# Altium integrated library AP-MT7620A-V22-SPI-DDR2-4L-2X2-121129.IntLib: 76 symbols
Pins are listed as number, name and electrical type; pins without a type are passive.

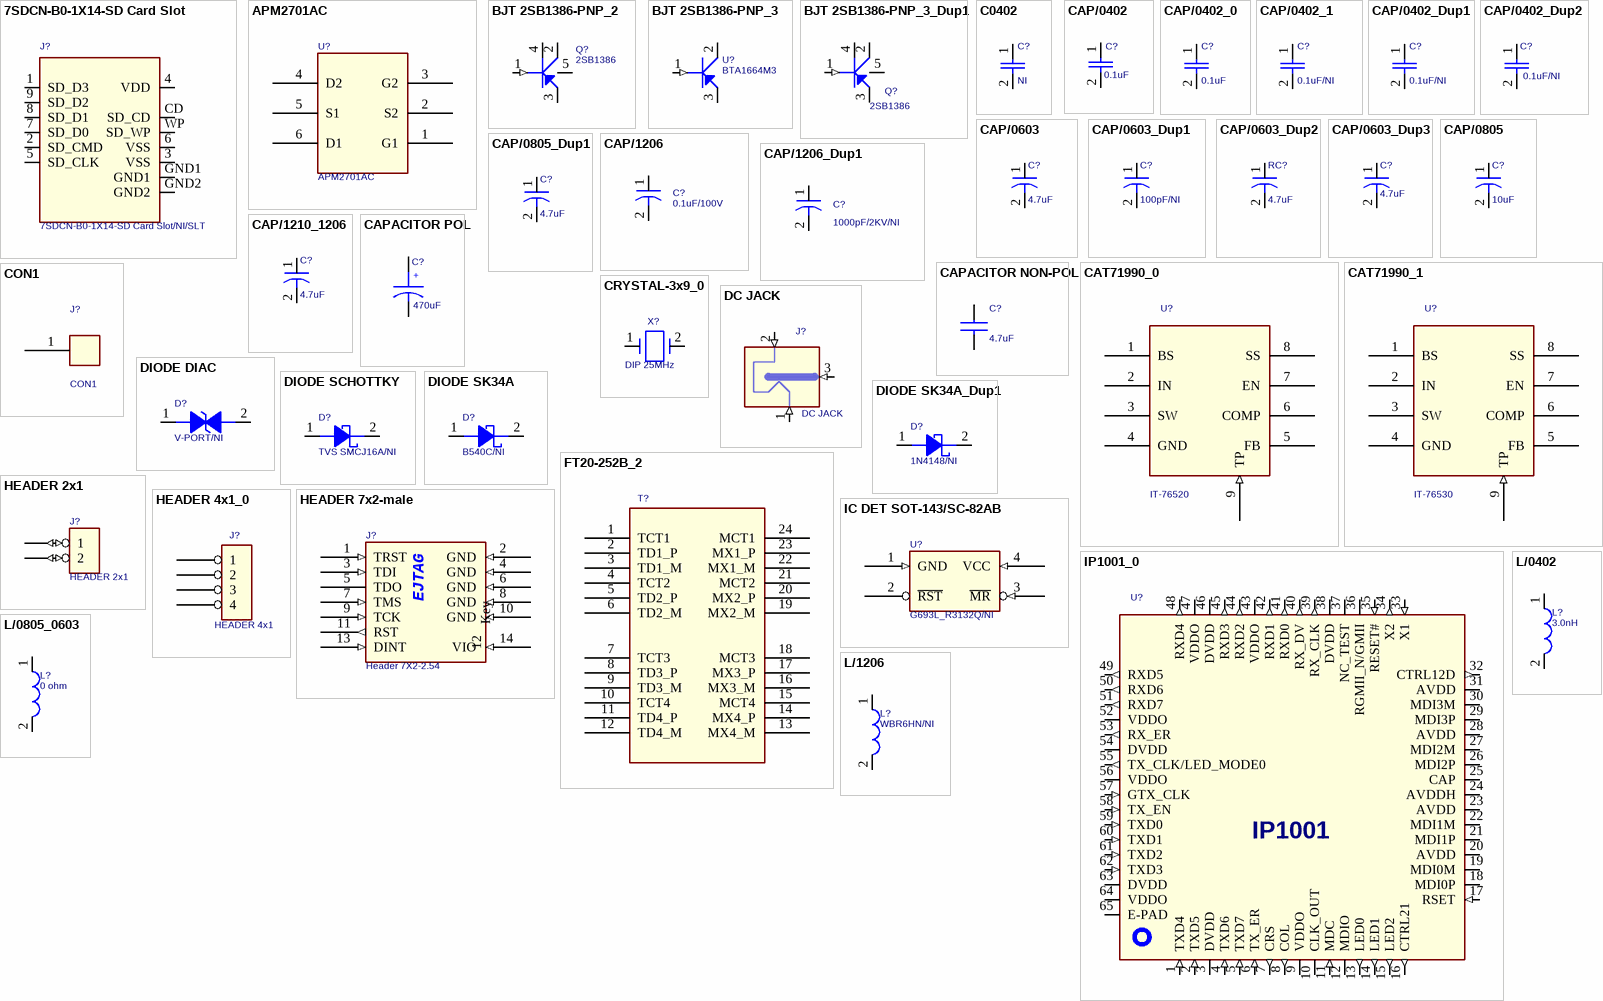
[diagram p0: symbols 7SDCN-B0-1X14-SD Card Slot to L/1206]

## 7SDCN-B0-1X14-SD Card Slot
designator J?, comment 7SDCN-B0-1X14-SD Card Slot/NI/SLT
footprint CON10P/SMD/R/F/7SDCN-B0-1X14
footprint CON10P/SMD/R/F/7SDCN-B0-1X14
pins: 1 SD_D3, 2 SD_CMD, 3 VSS, 4 VDD, 5 SD_CLK, 6 VSS, 7 SD_D0, 8 SD_D1, 9 SD_D2, CD SD_CD, GND1, GND2, WP SD_WP

## APM2701AC
designator U?
footprint SOT-23-6/SMD/P0.95/APM2701AC
pins: 1 G1, 2 S2, 3 G2, 4 D2, 5 S1, 6 D1

## BJT 2SB1386-PNP_2
designator Q?, comment 2SB1386
footprint SOT-89
footprint SOT-89/SMD/2SB1386
pins: 1 BASE (in), 2 COLLECTOR (io), 3 EMITTER (io), 4 COLLECTOR (io), 5 COLLECTOR (io)

## BJT 2SB1386-PNP_3
designator U?, comment BTA1664M3
footprint SOT-89
footprint SOT89/SMD
pins: 1 BASE (in), 2 COLLECTOR (io), 3 EMITTER (io)

## BJT 2SB1386-PNP_3_Dup1
designator Q?, comment 2SB1386
footprint SOT-89
footprint SOT-89/SMD/2SB1386
pins: 1 BASE (in), 2 COLLECTOR (power), 3 EMITTER (io), 4 COLLECTOR, 5 COLLECTOR

## C0402
designator C?, comment NI
footprint C0402
footprint C0402
pins: 1, 2

## CAP/0402
designator C?, comment 0.1uF
footprint 0402
footprint C0402
pins: 1 (io), 2 (io)

## CAP/0402_0
designator C?, comment 0.1uF
footprint 0402
footprint C0402
pins: 1, 2

## CAP/0402_1
designator C?, comment 0.1uF/NI
footprint 0402
footprint C0402
pins: 1, 2

## CAP/0402_Dup1
designator C?, comment 0.1uF/NI
footprint 0402
footprint C0402
pins: 1 (io), 2 (io)

## CAP/0402_Dup2
designator C?, comment 0.1uF/NI
1st Part Field: 0402
footprint 0402
footprint C0402
pins: 1, 2

## CAP/0603
designator C?, comment 4.7uF
footprint 0603
footprint C0603
pins: 1, 2

## CAP/0603_Dup1
designator C?, comment 100pF/NI
footprint 0603
footprint C0603
pins: 1, 2

## CAP/0603_Dup2
designator RC?, comment 4.7uF
footprint 0603
footprint C0603
pins: 1, 2

## CAP/0603_Dup3
designator C?, comment 4.7uF
footprint 0603
footprint C0603
pins: 1, 2

## CAP/0805
designator C?, comment 10uF
footprint 0805
footprint C0805
pins: 1, 2

## CAP/0805_Dup1
designator C?, comment 4.7uF
footprint 0805
footprint C0805
pins: 1, 2

## CAP/1206
designator C?, comment 0.1uF/100V
footprint 1206
footprint SB/1206
pins: 1, 2

## CAP/1206_Dup1
designator C?, comment 1000pF/2KV/NI
footprint 1206
footprint C1206
pins: 1, 2

## CAP/1210_1206
designator C?, comment 4.7uF
footprint 1210/1206
footprint C0805
pins: 1, 2

## CAPACITOR NON-POL
designator C?, comment 4.7uF
footprint C0603
pins: 1, 2

## CAPACITOR POL
designator C?, comment 470uF
footprint C470UF16V/D8H11
pins: 1, 2

## CAT71990_0
designator U?, comment IT-76520
footprint SOP8
footprint SOP8/SMD/P1.27/IT7653
pins: 1 BS, 2 IN, 3 SW, 4 GND, 5 FB, 6 COMP, 7 EN, 8 SS, 9 TP (in)

## CAT71990_1
designator U?, comment IT-76530
footprint SOP8
footprint SOP8/SMD/P1.27/IT7653
pins: 1 BS, 2 IN, 3 SW, 4 GND, 5 FB, 6 COMP, 7 EN, 8 SS, 9 TP (in)

## CON1
designator J?
footprint P1//M
pins: 1

## CRYSTAL-3x9_0
designator X?, comment DIP 25MHz
footprint XTAL-DIP-3X9
footprint CRYS/DIP/D5X10.6/GB2000025/eCERA
pins: 1, 2

## DC JACK
designator J?
footprint DC-JACK
footprint DC-JACK/3P/DIP/R/JD003-PF
pins: 1 (in), 2 (in), 3 (in)

## DIODE DIAC
designator D?, comment V-PORT/NI
PartNo: 3500-00000530
footprint C0603
pins: 1, 2

## DIODE SCHOTTKY
designator D?, comment TVS SMCJ16A/NI
footprint DO-214AB
footprint VARISTOR/SMD/TVM5B150L103RY
pins: 1 ANODE, 2 CATHODE

## DIODE SK34A
designator D?, comment B540C/NI
footprint DO-214AC
footprint D/SMD/P6.61/B540C
pins: 1 ANODE, 2 CATHODE

## DIODE SK34A_Dup1
designator D?, comment 1N4148/NI
footprint DO-214AC
footprint C0402
pins: 1 ANODE, 2 CATHODE

## FT20-252B_2
designator T?, comment FT20-252B  (value not drawn)
footprint TRANSFORMER/24P/SMD/HN2429CG
pins: 1 TCT1, 2 TD1_P, 3 TD1_M, 4 TCT2, 5 TD2_P, 6 TD2_M, 7 TCT3, 8 TD3_P, 9 TD3_M, 10 TCT4, 11 TD4_P, 12 TD4_M, 13 MX4_M, 14 MX4_P, 15 MCT4, 16 MX3_M, 17 MX3_P, 18 MCT3, 19 MX2_M, 20 MX2_P, 21 MCT2, 22 MX1_M, 23 MX1_P, 24 MCT1

## HEADER 2x1
designator J?
footprint P2x1-2.54mm
footprint DIP2/P2.54
pins: 1 (io), 2 (io)

## HEADER 4x1_0
designator J?, comment HEADER 4x1
footprint P4x1-2.54mm
footprint DIP4/P2.54
pins: 1, 2, 3, 4

## HEADER 7x2-male
designator J?, comment Header 7X2-2.54
footprint P7x2-2.54mm
footprint DIP7X2/P2.54
pins: 1 TRST (in), 2 GND (in), 3 TDI (in), 4 GND (in), 5 TDO (hiz), 6 GND (in), 7 TMS (in), 8 GND (in), 9 TCK (in), 10 GND (in), 11 RST (out), 12 Key, 13 DINT (in), 14 VIO (in)

## IC DET SOT-143/SC-82AB
designator U?, comment G693L_R3132Q/NI
footprint SOT-143/SC-82AB
footprint SOT-143/SMD/G693
pins: 1 GND (in), 2 ~{RST} (oc), 3 ~{MR} (in), 4 VCC (in)

## IP1001_0
designator U?, comment IP1001
footprint QFN64/SMD/P0.5/IP1001
pins: 1 TXD4 (in), 2 TXD5 (in), 3 DVDD (power), 4 TXD6 (in), 5 TXD7 (in), 6 TX_ER (in), 7 CRS (out), 8 COL (out), 9 VDDO (power), 10 CLK_OUT (power), 11 MDC (in), 12 MDIO (io), 13 LED0 (out), 14 LED1 (out), 15 LED2 (out), 16 CTRL21 (out), 17 RSET (in), 18 MDI0P (io), 19 MDI0M (io), 20 AVDD (power), 21 MDI1P (io), 22 MDI1M (io), 23 AVDD (power), 24 AVDDH (power), 25 CAP, 26 MDI2P (io), 27 MDI2M (io), 28 AVDD (power), 29 MDI3P (io), 30 MDI3M (io), 31 AVDD (power), 32 CTRL12D (out), 33 X1 (in), 34 X2 (out), 35 RESET# (in), 36 RGMII_N/GMII, 37 NC_TEST, 38 DVDD (power), 39 RX_CLK (out), 40 RX_DV (out), 41 RXD0 (out), 42 RXD1 (out), 43 VDDO (power), 44 RXD2 (out), 45 RXD3 (out), 46 DVDD (power), 47 VDDO (power), 48 RXD4 (out), 49 RXD5 (out), 50 RXD6 (out), 51 RXD7 (out), 52 VDDO (power), 53 RX_ER (out), 54 DVDD (power), 55 TX_CLK/LED_MODE0 (out), 56 VDDO (power), 57 GTX_CLK (in), 58 TX_EN (in), 59 TXD0 (in), 60 TXD1 (in), 61 TXD2 (in), 62 TXD3 (in), 63 DVDD (power), 64 VDDO (power), 65 E-PAD (power)

## L/0402
designator L?, comment 3.0nH
footprint 0402
footprint L0402
pins: 1, 2

## L/0805_0603
designator L?, comment 0 ohm
footprint 0805/0603
footprint L0805
pins: 1, 2

## L/1206
designator L?, comment WBR6HN/NI
footprint 1206
footprint L/IND/DIP/D6H14
pins: 1, 2

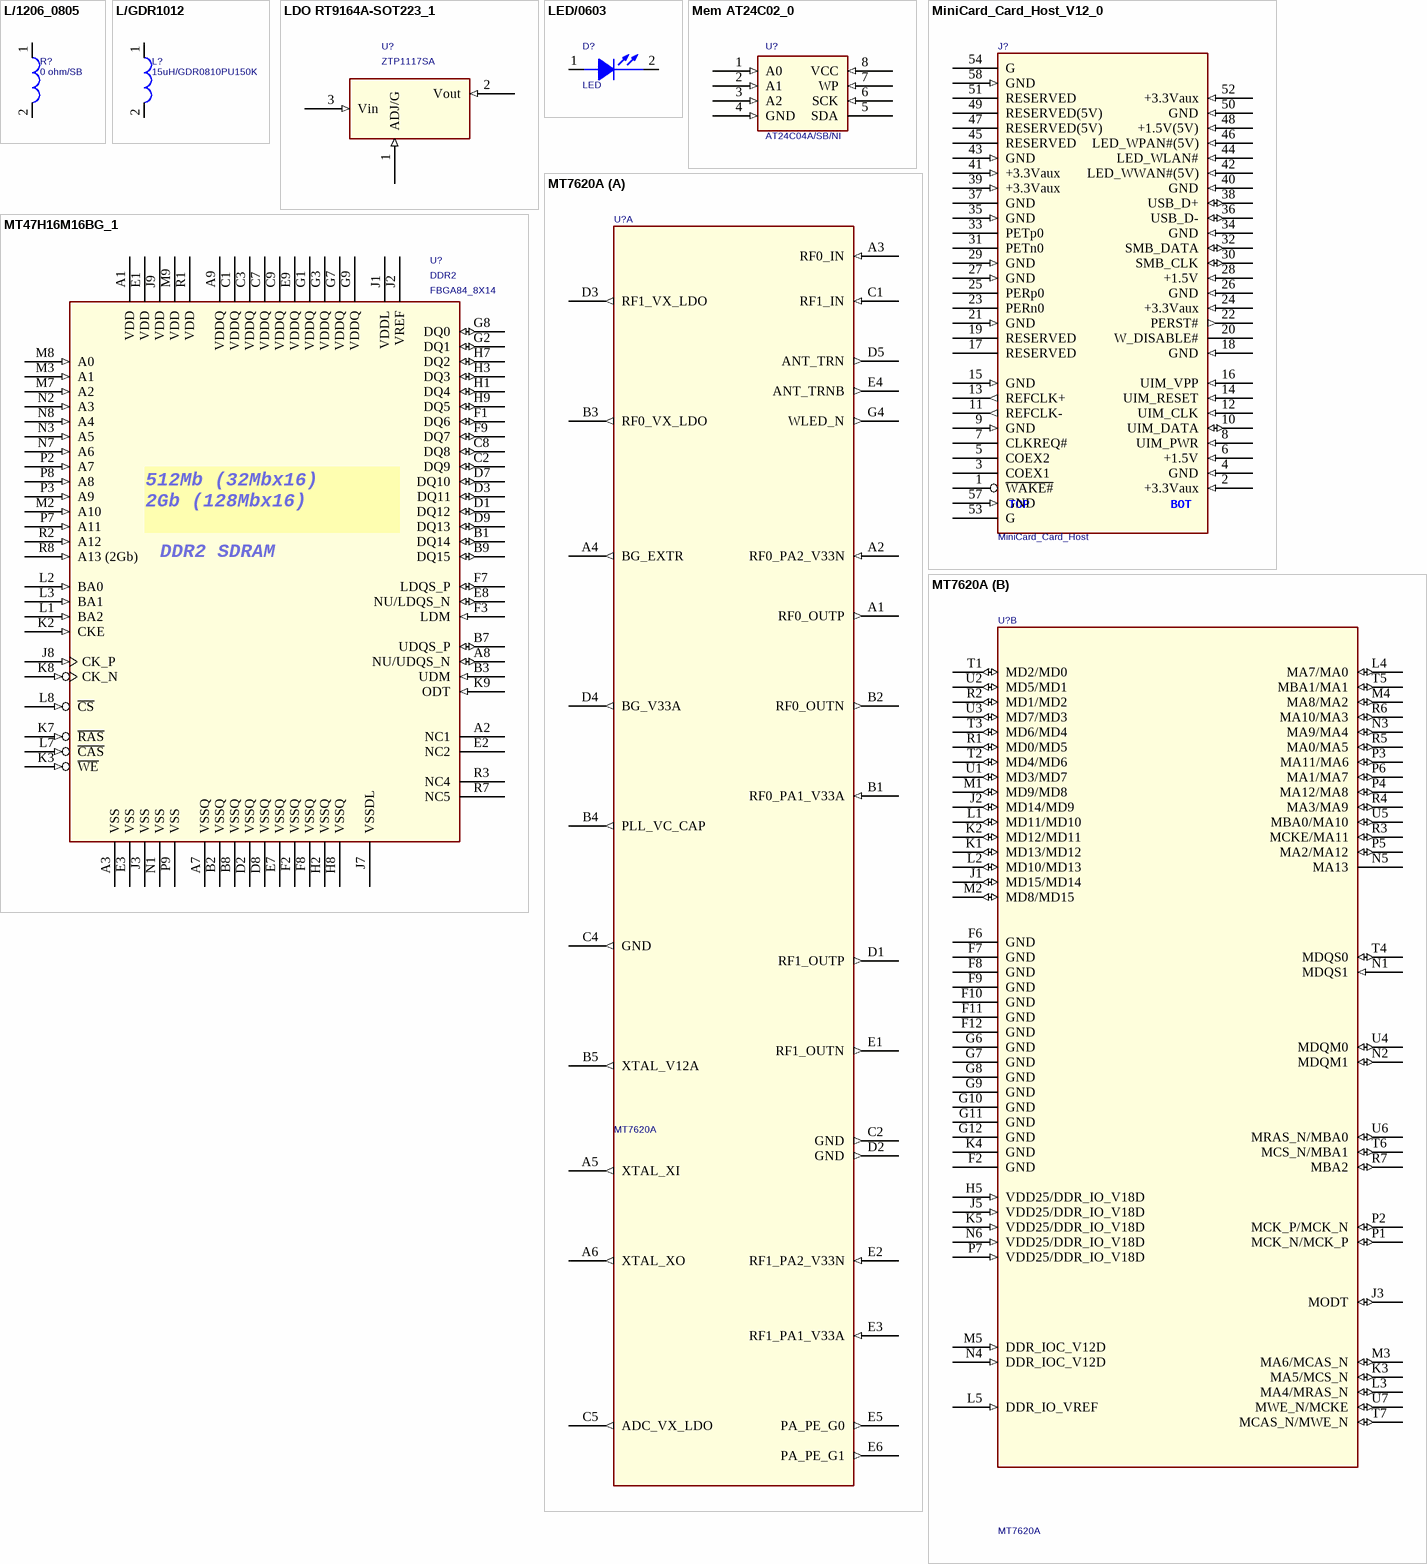
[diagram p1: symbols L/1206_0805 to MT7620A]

## L/1206_0805
designator R?, comment 0 ohm/SB
footprint 1206/0805
footprint SB/0603
pins: 1, 2

## L/GDR1012
designator L?, comment 15uH/GDR0810PU150K
footprint GDR-1012
footprint L/IND/DIP/MCD-0808-150MU-J
pins: 1, 2

## LDO RT9164A-SOT223_1
designator U?, comment ZTP1117SA
footprint SOT223-3/SMD/P2.3/AX1007
footprint SOT223-3/SMD/P2.3/AX1007
pins: 1 ADJ/G (in), 2 Vout (in), 3 Vin (in)

## LED/0603
designator D?, comment LED
footprint 0603
footprint C0603
pins: 1 ANODE, 2 CATHODE

## Mem AT24C02_0
designator U?, comment AT24C04A/SB/NI
footprint SOIC-8
footprint SOIC8/SMD/P1.27/AT24C04B-08B
pins: 1 A0 (in), 2 A1 (in), 3 A2 (in), 4 GND (in), 5 SDA, 6 SCK (in), 7 WP (in), 8 VCC (in)

## MiniCard_Card_Host_V12_0
designator J?, comment MiniCard_Card_Host
footprint PCIe-MiniCard-half
footprint MINI-PCI-Express/52P/SMD/R/F/C1720007
pins: 1 ~{WAKE#} (oc), 2 +3.3Vaux (in), 3 COEX1, 4 GND (in), 5 COEX2, 6 +1.5V (in), 7 CLKREQ# (oc), 8 UIM_PWR (in), 9 GND (in), 10 UIM_DATA (io), 11 REFCLK- (out), 12 UIM_CLK (in), 13 REFCLK+ (out), 14 UIM_RESET (in), 15 GND (in), 16 UIM_VPP (in), 17 RESERVED, 18 GND (in), 19 RESERVED, 20 W_DISABLE#, 21 GND (in), 22 PERST# (out), 23 PERn0, 24 +3.3Vaux (in), 25 PERp0, 26 GND (in), 27 GND (in), 28 +1.5V (in), 29 GND (in), 30 SMB_CLK (io), 31 PETn0, 32 SMB_DATA (io), 33 PETp0, 34 GND (in), 35 GND (in), 36 USB_D- (io), 37 GND (power), 38 USB_D+ (io), 39 +3.3Vaux (in), 40 GND (in), 41 +3.3Vaux (in), 42 LED_WWAN#(5V) (in), 43 GND (in), 44 LED_WLAN# (in), 45 RESERVED, 46 LED_WPAN#(5V) (in), 47 RESERVED(5V), 48 +1.5V(5V) (in), 49 RESERVED(5V), 50 GND (in), 51 RESERVED, 52 +3.3Vaux (in), 53 G, 54 G, 57 GND (in), 58 GND (in)

## MT47H16M16BG_1
designator U?, comment DDR2  Package: FBGA84_8X14
IC-SDRAM-MT47H-FBGA84; NC: A2,E2,L1,R3,R7,R8; Vendor PN: MT47H16M16BG-5E; Vendor: MICRON; Description 2: 5nS 32MX16 DDR2; P_Number: xx; P_Description: W9725G6IB
footprint WBGA84/SMD/P0.8/W9751G6IB
pins: A1 VDD (power), A2 NC1, A3 VSS (power), A7 VSSQ (power), A8 NU/UDQS_N (io), A9 VDDQ (power), B1 DQ14 (io), B2 VSSQ (power), B3 UDM (in), B7 UDQS_P (io), B8 VSSQ (power), B9 DQ15 (io), C1 VDDQ (power), C2 DQ9 (io), C3 VDDQ (power), C7 VDDQ (power), C8 DQ8 (io), C9 VDDQ (power), D1 DQ12 (io), D2 VSSQ (power), D3 DQ11 (io), D7 DQ10 (io), D8 VSSQ (power), D9 DQ13 (io), E1 VDD (power), E2 NC2, E3 VSS (power), E7 VSSQ (power), E8 NU/LDQS_N (io), E9 VDDQ (power), F1 DQ6 (io), F2 VSSQ (power), F3 LDM (in), F7 LDQS_P (io), F8 VSSQ (power), F9 DQ7 (io), G1 VDDQ (power), G2 DQ1 (io), G3 VDDQ (power), G7 VDDQ (power), G8 DQ0 (io), G9 VDDQ (power), H1 DQ4 (io), H2 VSSQ (power), H3 DQ3 (io), H7 DQ2 (io), H8 VSSQ (power), H9 DQ5 (io), J1 VDDL (power), J2 VREF (power), J3 VSS (power), J7 VSSDL (power), J8 CK_P (in), J9 VDD (power), K2 CKE (in), K3 ~{WE} (in), K7 ~{RAS} (in), K8 CK_N (in), K9 ODT (in), L1 BA2 (in), L2 BA0 (in), L3 BA1 (in), L7 ~{CAS} (in), L8 ~{CS} (in), M2 A10 (in), M3 A1 (in), M7 A2 (in), M8 A0 (in), M9 VDD (power), N1 VSS (power), N2 A3 (in), N3 A5 (in), N7 A6 (in), N8 A4 (in), P2 A7 (in), P3 A9 (in), P7 A11 (in), P8 A8 (in), P9 VSS (power), R1 VDD (power), R2 A12 (in), R3 NC4, R7 NC5, R8 A13 (2Gb) (in)

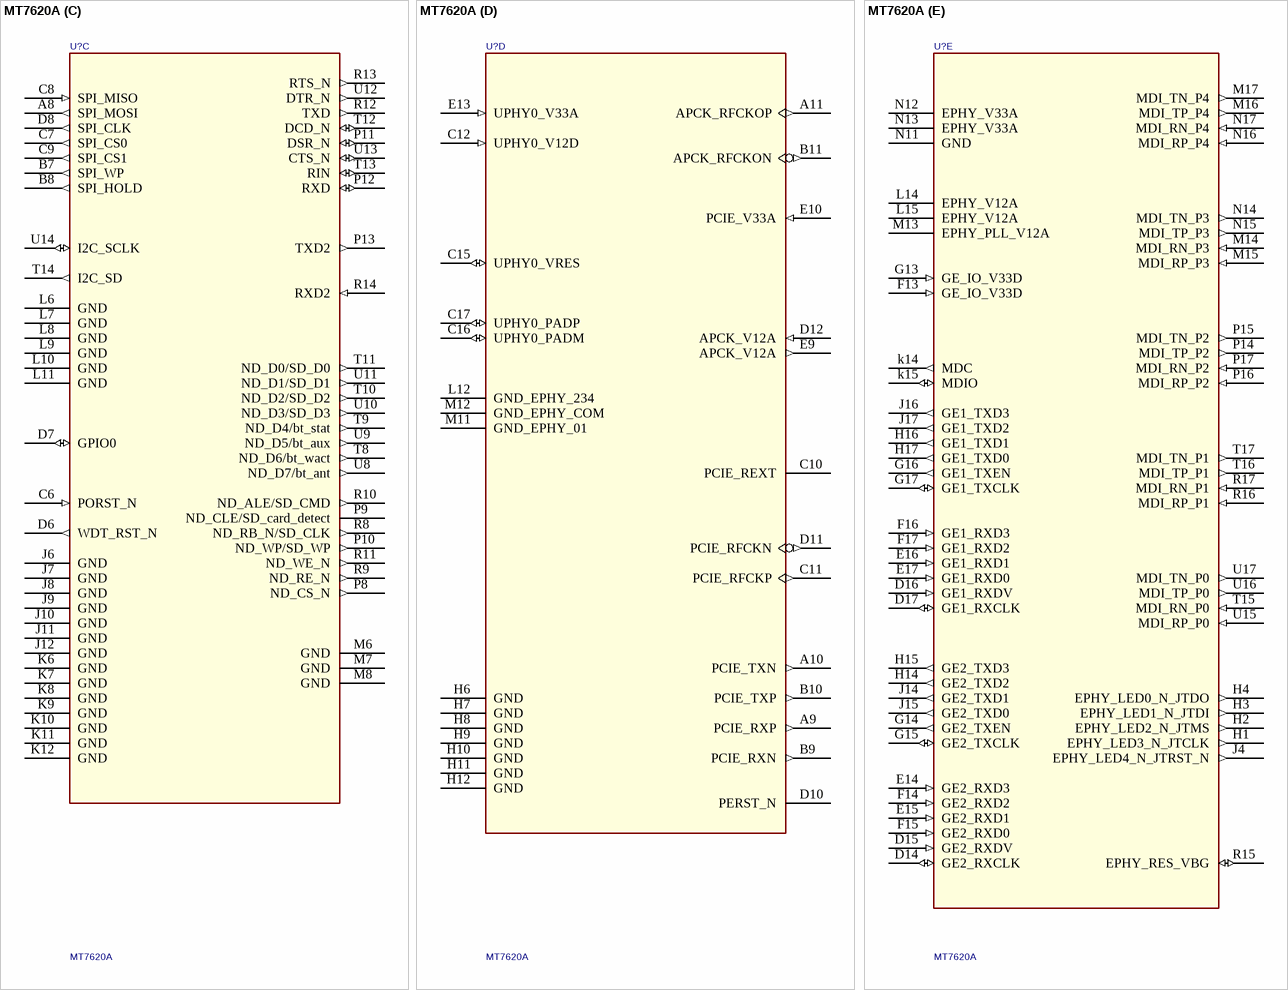
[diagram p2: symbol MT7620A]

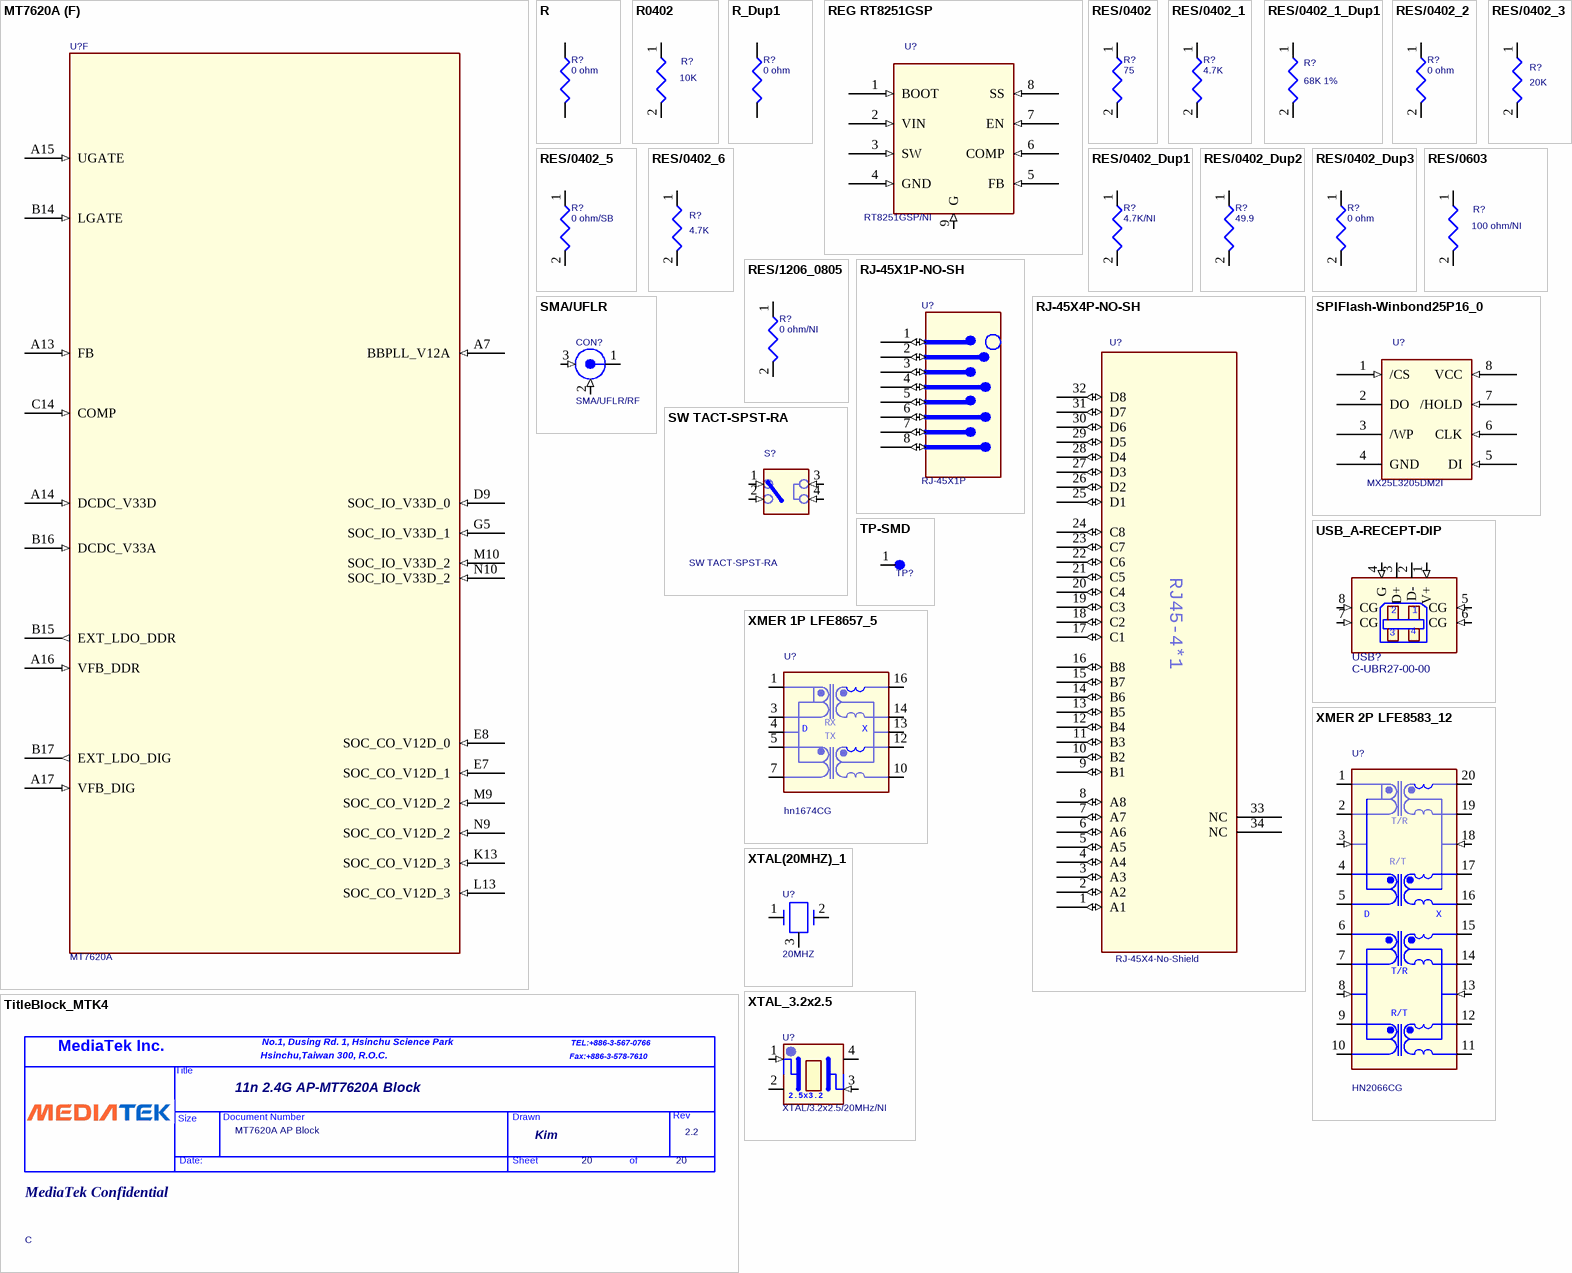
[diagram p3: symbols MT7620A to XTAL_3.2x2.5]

## MT7620A
designator U?
footprint MT7620AE2/TFBGA265/P0.65/B0.3/11X11
footprint MT7620AE2/TFBGA265/P0.65/B0.3/11X11
part A pins: A1 RF0_OUTP (out), A2 RF0_PA2_V33N (in), A3 RF0_IN (in), A4 BG_EXTR (out), A5 XTAL_XI (out), A6 XTAL_XO (out), B1 RF0_PA1_V33A (in), B2 RF0_OUTN (out), B3 RF0_VX_LDO (out), B4 PLL_VC_CAP (out), B5 XTAL_V12A (out), C1 RF1_IN (in), C2 GND (out), C4 GND (out), C5 ADC_VX_LDO (out), D1 RF1_OUTP (out), D2 GND (out), D3 RF1_VX_LDO (out), D4 BG_V33A (out), D5 ANT_TRN (out), E1 RF1_OUTN (out), E2 RF1_PA2_V33N (in), E3 RF1_PA1_V33A (in), E4 ANT_TRNB (out), E5 PA_PE_G0 (out), E6 PA_PE_G1 (out), G4 WLED_N (out)
part B pins: F2 GND (power), F6 GND (power), F7 GND (power), F8 GND (power), F9 GND (power), F10 GND (power), F11 GND (power), F12 GND (power), G6 GND (power), G7 GND (power), G8 GND (power), G9 GND (power), G10 GND (power), G11 GND (power), G12 GND (power), H5 VDD25/DDR_IO_V18D (in), J1 MD15/MD14 (io), J2 MD14/MD9 (io), J3 MODT (io), J5 VDD25/DDR_IO_V18D (in), K1 MD13/MD12 (io), K2 MD12/MD11 (io), K3 MA5/MCS_N (io), K4 GND (power), K5 VDD25/DDR_IO_V18D (in), L1 MD11/MD10 (io), L2 MD10/MD13 (io), L3 MA4/MRAS_N (io), L4 MA7/MA0 (io), L5 DDR_IO_VREF (in), M1 MD9/MD8 (io), M2 MD8/MD15 (io), M3 MA6/MCAS_N (io), M4 MA8/MA2 (io), M5 DDR_IOC_V12D (in), N1 MDQS1 (in), N2 MDQM1 (io), N3 MA9/MA4 (io), N4 DDR_IOC_V12D (in), N5 MA13, N6 VDD25/DDR_IO_V18D (in), P1 MCK_N/MCK_P (io), P2 MCK_P/MCK_N (io), P3 MA11/MA6 (io), P4 MA12/MA8 (io), P5 MA2/MA12 (io), P6 MA1/MA7 (io), P7 VDD25/DDR_IO_V18D (in), R1 MD0/MD5 (io), R2 MD1/MD2 (io), R3 MCKE/MA11 (io), R4 MA3/MA9 (io), R5 MA0/MA5 (io), R6 MA10/MA3 (io), R7 MBA2 (io), T1 MD2/MD0 (io), T2 MD4/MD6 (io), T3 MD6/MD4 (io), T4 MDQS0 (io), T5 MBA1/MA1 (io), T6 MCS_N/MBA1 (io), T7 MCAS_N/MWE_N (io), U1 MD3/MD7 (io), U2 MD5/MD1 (io), U3 MD7/MD3 (io), U4 MDQM0 (io), U5 MBA0/MA10 (io), U6 MRAS_N/MBA0 (io), U7 MWE_N/MCKE (io)
part C pins: A8 SPI_MOSI (out), B7 SPI_WP (out), B8 SPI_HOLD (out), C6 PORST_N (in), C7 SPI_CS0 (out), C8 SPI_MISO (in), C9 SPI_CS1 (out), D6 WDT_RST_N (out), D7 GPIO0 (io), D8 SPI_CLK (out), J6 GND (power), J7 GND (power), J8 GND (power), J9 GND (power), J10 GND (power), J11 GND (power), J12 GND (power), K6 GND (power), K7 GND (power), K8 GND (power), K9 GND (power), K10 GND (power), K11 GND (power), K12 GND (power), L6 GND (power), L7 GND (power), L8 GND (power), L9 GND (power), L10 GND (power), L11 GND (power), M6 GND (power), M7 GND (power), M8 GND (power), P8 ND_CS_N (out), P9 ND_CLE/SD_card_detect, P10 ND_WP/SD_WP (out), P11 DSR_N (io), P12 RXD (io), P13 TXD2 (out), R8 ND_RB_N/SD_CLK (out), R9 ND_RE_N (out), R10 ND_ALE/SD_CMD (out), R11 ND_WE_N (out), R12 TXD (out), R13 RTS_N (out), R14 RXD2 (in), T8 ND_D6/bt_wact (out), T9 ND_D4/bt_stat (out), T10 ND_D2/SD_D2 (out), T11 ND_D0/SD_D0 (out), T12 DCD_N (io), T13 RIN (io), T14 I2C_SD (out), U8 ND_D7/bt_ant (out), U9 ND_D5/bt_aux (out), U10 ND_D3/SD_D3 (out), U11 ND_D1/SD_D1 (out), U12 DTR_N (out), U13 CTS_N (io), U14 I2C_SCLK (io)
part D pins: A9 PCIE_RXP (out), A10 PCIE_TXN (out), A11 APCK_RFCKOP (out), B9 PCIE_RXN (out), B10 PCIE_TXP (out), B11 APCK_RFCKON (out), C10 PCIE_REXT, C11 PCIE_RFCKP (out), C12 UPHY0_V12D (in), C15 UPHY0_VRES (io), C16 UPHY0_PADM (io), C17 UPHY0_PADP (io), D10 PERST_N, D11 PCIE_RFCKN (out), D12 APCK_V12A (in), E9 APCK_V12A (out), E10 PCIE_V33A (in), E13 UPHY0_V33A (in), H6 GND (power), H7 GND (power), H8 GND (power), H9 GND (power), H10 GND (power), H11 GND (power), H12 GND (power), L12 GND_EPHY_234 (power), M11 GND_EPHY_01 (power), M12 GND_EPHY_COM (power)
part E pins: D14 GE2_RXCLK (io), D15 GE2_RXDV (in), D16 GE1_RXDV (in), D17 GE1_RXCLK (io), E14 GE2_RXD3 (in), E15 GE2_RXD1 (in), E16 GE1_RXD1 (in), E17 GE1_RXD0 (in), F13 GE_IO_V33D (in), F14 GE2_RXD2 (in), F15 GE2_RXD0 (in), F16 GE1_RXD3 (in), F17 GE1_RXD2 (in), G13 GE_IO_V33D (in), G14 GE2_TXEN (out), G15 GE2_TXCLK (io), G16 GE1_TXEN (out), G17 GE1_TXCLK (io), H1 EPHY_LED3_N_JTCLK (out), H2 EPHY_LED2_N_JTMS (out), H3 EPHY_LED1_N_JTDI (out), H4 EPHY_LED0_N_JTDO (out), H14 GE2_TXD2 (out), H15 GE2_TXD3 (out), H16 GE1_TXD1 (out), H17 GE1_TXD0 (out), J4 EPHY_LED4_N_JTRST_N (out), J14 GE2_TXD1 (out), J15 GE2_TXD0 (out), J16 GE1_TXD3 (out), J17 GE1_TXD2 (out), k14 MDC (out), k15 MDIO (io), L14 EPHY_V12A (power), L15 EPHY_V12A (power), M13 EPHY_PLL_V12A (power), M14 MDI_RN_P3 (in), M15 MDI_RP_P3 (in), M16 MDI_TP_P4 (out), M17 MDI_TN_P4 (out), N11 GND (power), N12 EPHY_V33A (power), N13 EPHY_V33A (power), N14 MDI_TN_P3 (out), N15 MDI_TP_P3 (out), N16 MDI_RP_P4 (in), N17 MDI_RN_P4 (in), P14 MDI_TP_P2 (out), P15 MDI_TN_P2 (out), P16 MDI_RP_P2 (in), P17 MDI_RN_P2 (in), R15 EPHY_RES_VBG (io), R16 MDI_RP_P1 (in), R17 MDI_RN_P1 (in), T15 MDI_RN_P0 (in), T16 MDI_TP_P1 (out), T17 MDI_TN_P1 (out), U15 MDI_RP_P0 (in), U16 MDI_TP_P0 (out), U17 MDI_TN_P0 (out)
part F pins: A7 BBPLL_V12A (in), A13 FB (in), A14 DCDC_V33D (in), A15 UGATE (in), A16 VFB_DDR (in), A17 VFB_DIG (in), B14 LGATE (in), B15 EXT_LDO_DDR (out), B16 DCDC_V33A (in), B17 EXT_LDO_DIG (out), C14 COMP (in), D9 SOC_IO_V33D_0 (in), E7 SOC_CO_V12D_1 (in), E8 SOC_CO_V12D_0 (in), G5 SOC_IO_V33D_1 (in), K13 SOC_CO_V12D_3 (in), L13 SOC_CO_V12D_3 (in), M9 SOC_CO_V12D_2 (in), M10 SOC_IO_V33D_2 (in), N9 SOC_CO_V12D_2 (in), N10 SOC_IO_V33D_2 (in)

## R
designator R?, comment 0 ohm
Resistor, 0603, 5%; Part Number: 110-110-00100; Manufacturer: �j驾�歆�; Class: 1R-0402; Key: 3162U-N14-V11-#449; SDTSourceLibName: C:\WINDOWS\TEMP\2GM.LIB; V1: 25V 20%; By: Ralink; HYP_Type: (R; BOM_Class: Chipset
footprint L0805
pins: 1, 2

## R0402
designator R?, comment 10K
footprint R0402
footprint R0402
pins: 1, 2

## R_Dup1
designator R?, comment 0 ohm
footprint R0805
pins: 1, 2

## REG RT8251GSP
designator U?, comment RT8251GSP/NI
footprint SOIC-8P-EP
footprint SOP8/SMD/P1.27/RT8251
pins: 1 BOOT (in), 2 VIN (in), 3 SW (in), 4 GND (in), 5 FB (in), 6 COMP (in), 7 EN (in), 8 SS (in), 9 G (in)

## RES/0402
designator R?, comment 75
footprint 0402
footprint R0402
pins: 1 (io), 2 (io)

## RES/0402_1
designator R?, comment 4.7K
footprint 0402
footprint R0402
pins: 1, 2

## RES/0402_1_Dup1
designator R?, comment 68K 1%
footprint 0402
footprint R0402
pins: 1, 2

## RES/0402_2
designator R?, comment 0 ohm
footprint 0402
footprint R0402
pins: 1, 2

## RES/0402_3
designator R?, comment 20K
footprint 0402
footprint R0402
pins: 1, 2

## RES/0402_5
designator R?, comment 0 ohm/SB
footprint 0402
footprint SB/0402
pins: 1, 2

## RES/0402_6
designator R?, comment 4.7K
footprint 0402
footprint R0402
pins: 1, 2

## RES/0402_Dup1
designator R?, comment 4.7K/NI
footprint 0402
footprint R0402
pins: 1 (io), 2 (io)

## RES/0402_Dup2
designator R?, comment 49.9
footprint 0402
footprint R0402
pins: 1 (io), 2 (io)

## RES/0402_Dup3
designator R?, comment 0 ohm
footprint 0402
footprint R0402
pins: 1 (io), 2 (io)

## RES/0603
designator R?, comment 100 ohm/NI
footprint 0603
footprint R0603
pins: 1 (io), 2 (io)

## RES/1206_0805
designator R?, comment 0 ohm/NI
footprint 1206/0805
footprint C1206
pins: 1 (io), 2 (io)

## RJ-45X1P-NO-SH
designator U?, comment RJ-45X1P
footprint RJ45A-NO-SH
footprint RJ45/8P/DIP/R/8208C-B01
pins: 1 P1 (io), 2 P2 (io), 3 P3 (io), 4 P4 (io), 5 P5 (io), 6 P6 (io), 7 P7 (io), 8 P8 (io)

## RJ-45X4P-NO-SH
designator U?, comment RJ-45X4-No-Shield
footprint RJ45-4P-NO-SH
footprint RJ45/32P/DIP/R/N3642-001
pins: 1 A1 (io), 2 A2 (io), 3 A3 (io), 4 A4 (io), 5 A5 (io), 6 A6 (io), 7 A7 (io), 8 A8 (io), 9 B1 (io), 10 B2 (io), 11 B3 (io), 12 B4 (io), 13 B5 (io), 14 B6 (io), 15 B7 (io), 16 B8 (io), 17 C1 (io), 18 C2 (io), 19 C3 (io), 20 C4 (io), 21 C5 (io), 22 C6 (io), 23 C7 (io), 24 C8 (io), 25 D1 (io), 26 D2 (io), 27 D3 (io), 28 D4 (io), 29 D5 (io), 30 D6 (io), 31 D7 (io), 32 D8 (io), 33 NC, 34 NC

## SMA/UFLR
designator CON?, comment SMA/UFLR/RF
footprint UFLR
footprint COAXIAL/SMD/CON/V/I-PEX/W08-5801
pins: 1, 2 (in), 3 GNDA (in)

## SPIFlash-Winbond25P16_0
designator U?, comment MX25L3205DM2I
footprint SOIC8/SMD/P1.27/AT26DF321
pins: 1 /CS (in), 2 DO, 3 /WP, 4 GND, 5 DI (in), 6 CLK (in), 7 /HOLD (in), 8 VCC (in)

## SW TACT-SPST-RA
designator S?
footprint SW2P
footprint SW/4P/DIP/TS02-CN-PF
pins: 1 (in), 2 (in), 3 (in), 4 (in)

## TitleBlock_MTK4
designator *?  PIM: MediaTek Confidential  Page Count: 20  Page Size: C  Title: 11n 2.4G AP-MT7620A Block  RevCode: 2.2  Doc: MT7620A AP Block  Designer: Kim  (hidden comment: TitleBlock_MTK4)  (graphical)

## TP-SMD
designator TP?, comment SMD  (value not drawn)
footprint TP-SMD
footprint PAD/1P/0.5MM
pins: 1

## USB_A-RECEPT-DIP
designator USB?, comment C-UBR27-00-00
Schematics' Source Library: C:\MSim_8\UserLib\vnet2.slb
footprint USB_A-RECEPT-R/A-DIP
footprint USB/4P/P2.0/DIP/R/F/SUA-110VB-B2N
pins: 1 V+ (in), 2 D- (hiz), 3 D+ (hiz), 4 G (in), 5 CG (in), 6 CG (in), 7 CG (in), 8 CG (in)

## XMER 1P LFE8657_5
designator U?, comment hn1674CG
footprint DIP-16PIN-2010
footprint TRANSFORMER/16P/DIP/HN1674CG
pins: 1 RD+ (io), 3 RD- (io), 4 CT (io), 5 TD+ (io), 7 TD- (io), 10 TX- (io), 12 TX+ (io), 13 CG (io), 14 RX- (io), 16 RX+ (io)

## XMER 2P LFE8583_12
designator U?, comment HN2066CG
footprint DIP-20PIN-2510
footprint TRANSFORMER/20P/DIP/HN2066CG
pins: 1 TRD+1 (io), 2 TRD-1 (io), 3 CT1 (in), 4 RTD+1 (io), 5 RTD-1 (io), 6 TRD+2 (io), 7 TRD+2 (io), 8 CT2 (in), 9 RTD+2 (io), 10 RTD-2 (io), 11 RTX-2 (io), 12 RTX+2 (io), 13 CTX2 (in), 14 TRX-1 (io), 15 TRX+2 (io), 16 RTX-1 (io), 17 RTX+1 (io), 18 CTX1 (in), 19 TRX-1 (io), 20 TRX+1 (io)

## XTAL(20MHZ)_1
designator U?, comment 20MHZ
Parnt_desc: XTAL 20MHz 30ppm HC-49/U; Parent: 24-020060-40
footprint DIP
footprint CRYS/DIP/D5X10.6/GB2000025/eCERA
pins: 1, 2, 3

## XTAL_3.2x2.5
designator U?, comment XTAL/3.2x2.5/20MHz/NI
footprint XTAL-SMD/3.2X2.5
footprint CRYS/SMD/D3.2X2.5/E3SB40/HOSONIC
pins: 1 X1 (in), 2 NC, 3 X2 (in), 4 NC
